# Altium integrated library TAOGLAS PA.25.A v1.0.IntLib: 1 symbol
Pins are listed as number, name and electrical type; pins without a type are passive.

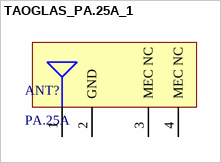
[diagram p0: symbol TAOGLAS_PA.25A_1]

## TAOGLAS_PA.25A_1
designator ANT?, comment PA.25A
ANTENNA SMT 800MHz ~ 2200 MHZ; ComponentLibStatus: Created; MFG: Taoglas; Temp_High: +85C; Temp_Low: -40C
footprint TAOGLAS_PA.25A (SMT 800MHZ ~ 2200MHz)
pins: 1 RF OUT, 2 GND, 3 MEC NC, 4 MEC NC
